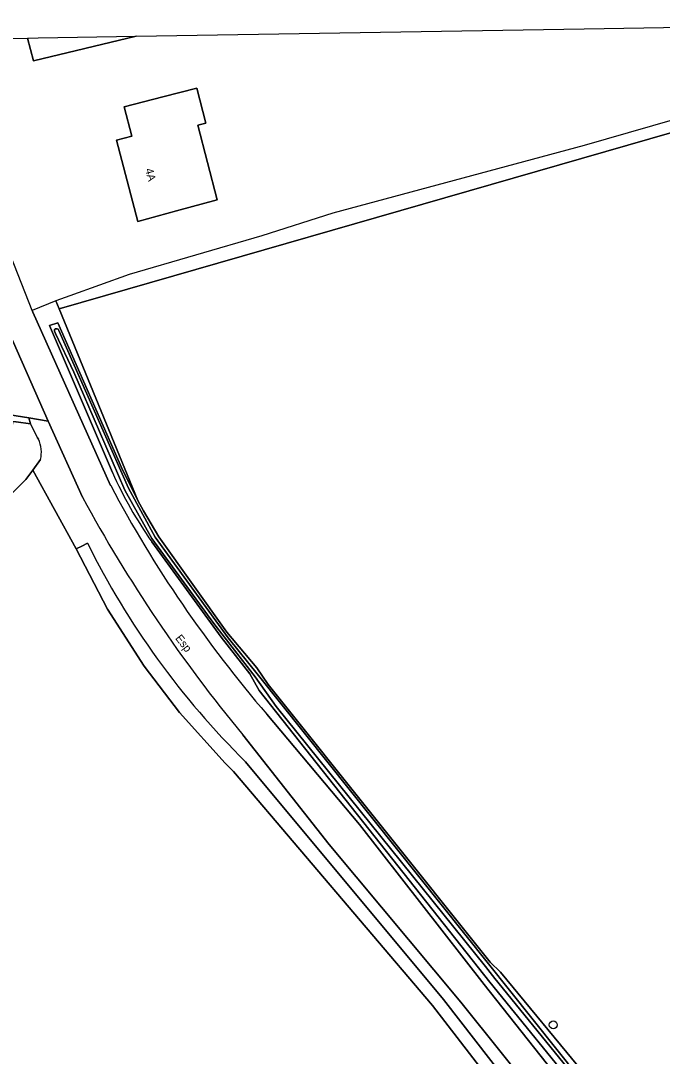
# Model space of a CAD drawing. Extents: x 161385 to 162589, y 388479 to 389756.
# Drawn here: x 162429.6 to 162509.8, y 389626.2 to 389755.6 of the extents above; entities that cross this region are included whole.
import ezdxf

# ---------------------------------------------------------------- set-up
doc = ezdxf.new("R2010")
doc.units = 0
for name, color, linetype in [('IMGEO_Boom', 7, 'Continuous'), ('IMGEO_Bouwland', 7, 'Continuous'), ('IMGEO_Erf', 7, 'Continuous'), ('IMGEO_Grasland_overig', 7, 'Continuous'), ('IMGEO_Groenvoorziening', 7, 'Continuous'), ('IMGEO_Hek', 7, 'Continuous'), ('IMGEO_Oever', 7, 'Continuous'), ('IMGEO_Openbare_ruimte_label', 7, 'Continuous'), ('IMGEO_Pand', 7, 'Continuous'), ('IMGEO_Pand_nummerreeks', 7, 'Continuous'), ('IMGEO_Rijbaan_lokaal_gesloten', 7, 'Continuous'), ('IMGEO_Rijbaan_lokaal_open', 7, 'Continuous'), ('IMGEO_Waterloop', 7, 'Continuous')]:
    doc.layers.add(name, color=color, linetype=linetype)

msp = doc.modelspace()

# ---------------------------------------------------------------- linework, layer by layer
at = {"layer": 'IMGEO_Boom'}
msp.add_circle((162496.15, 389630.11), 0.489, dxfattribs=at)
at = {"layer": 'IMGEO_Bouwland'}
for points in [[(162559.43, 389755.58), (162434.43, 389719.57), (162444.28, 389695.63), (162444.98, 389694.35), (162446.88, 389691.1), (162455.38, 389679.17), (162459.14, 389674.72), (162460.55, 389672.64), (162488.26, 389637.95), (162489.58, 389636.69), (162500, 389624.02)], [(162496.19, 389612.91), (162481.08, 389632.53), (162456.22, 389661.77), (162455.16, 389662.82), (162449.46, 389669.13), (162445.05, 389674.92), (162440.48, 389682.07), (162436.57, 389689.6), (162431.13, 389699.42), (162430.29, 389698.26), (162425.82, 389693.87), (162416.7, 389686.29), (162405.96, 389676.81), (162402.25, 389673.34), (162397.7, 389669.06), (162385.15, 389658.37), (162325.08, 389605.29), (162324.14, 389604.46), (162322.11, 389602.67), (162322.8, 389597.7), (162339.42, 389588), (162346.95, 389583.61), (162347.95, 389566.2), (162352.65, 389567.29)]]:
    msp.add_lwpolyline(points, dxfattribs=at)
at = {"layer": 'IMGEO_Erf'}
for points in [[(162444.07, 389753.64), (162500, 389754.58), (162552.12, 389755.46), (162552.12, 389755.46), (162552.12, 389755.46), (162534.43, 389750), (162528.09, 389748.05), (162500, 389739.97), (162468.6, 389731.52), (162459.77, 389728.7), (162443.19, 389723.89), (162435.78, 389721.2), (162434.02, 389720.56), (162431.05, 389719.38), (162426.09, 389732), (162425, 389736.75), (162419.72, 389750), (162418.44, 389753.21), (162430.5, 389753.41), (162431.25, 389750.55)], [(162451.63, 389747.16), (162452.77, 389742.79), (162451.76, 389742.53), (162454.18, 389733.21), (162449.11, 389731.82), (162444.28, 389730.5), (162441.6, 389740.67), (162443.51, 389741.17), (162442.55, 389744.8), (162447.39, 389746.06)]]:
    msp.add_lwpolyline(points, close=True, dxfattribs=at)
for points in [[(162444.07, 389753.64), (162431.25, 389750.55), (162430.5, 389753.41), (162431.8, 389753.43), (162444.07, 389753.64)], [(162428.38, 389704.2), (162428.56, 389705.01), (162428.62, 389705.29), (162428.66, 389705.5), (162429.02, 389705.46), (162429.08, 389705.45), (162430.85, 389705.23), (162430.63, 389705.94), (162416.62, 389708.17), (162415.83, 389707.79), (162364.15, 389682.86), (162364.04, 389682.81), (162386.14, 389662.75), (162389.24, 389665.14), (162390.05, 389665.76), (162402.57, 389677.34), (162410.94, 389684.45)]]:
    msp.add_lwpolyline(points, dxfattribs=at)
at = {"layer": 'IMGEO_Grasland_overig'}
msp.add_lwpolyline([(162559.43, 389755.58), (162552.12, 389755.46), (162552.12, 389755.46), (162534.43, 389750), (162528.09, 389748.05), (162500, 389739.97), (162468.6, 389731.52), (162459.77, 389728.7), (162443.19, 389723.89), (162435.78, 389721.2), (162434.02, 389720.56), (162434.43, 389719.57)], close=True, dxfattribs=at)
at = {"layer": 'IMGEO_Groenvoorziening'}
for points in [[(162441.08, 389699.13), (162433.24, 389717.49), (162434.28, 389717.85), (162442.23, 389699.76), (162444.28, 389695.63), (162434.43, 389719.57), (162434.02, 389720.56), (162431.05, 389719.38), (162431.13, 389719.17), (162440.87, 389697.49)], [(162437.34, 389696.04), (162433.05, 389705.55), (162430.63, 389705.94), (162430.85, 389705.23), (162431.75, 389703.46), (162431.84, 389703.29)], [(162432.1, 389700.75), (162431.13, 389699.42), (162436.57, 389689.6), (162437.27, 389689.94), (162437.99, 389690.29)], [(162500, 389620.97), (162488.25, 389635.43), (162459.4, 389671.88), (162458.24, 389673.98), (162454.69, 389678.56), (162446, 389690.46)], [(162460.38, 389668.93), (162471.96, 389655.14), (162487.54, 389635.16), (162500, 389619.35), (162502.33, 389616.39), (162507.6, 389609.95), (162508.18, 389609.16)], [(162484.59, 389632.95), (162468.15, 389652.66), (162457.37, 389666.34)], [(162457.73, 389662.99), (162482.44, 389633.29), (162495.86, 389616), (162501.86, 389608.05), (162500.82, 389607.06), (162500.28, 389606.55), (162496.89, 389610.48), (162485.48, 389604.32), (162481.25, 389602.12)], [(162499.72, 389614.08), (162484.59, 389632.95)]]:
    msp.add_lwpolyline(points, dxfattribs=at)
for centre, radius, start, end in [((162428.42, 389701.65), 3.8, 346.2941, 25.5475), ((162491.3, 389721.86), 55.12, 204.352, 214.7256), ((162577.72, 389770.02), 154.88, 207.9239, 220.748), ((162603.51, 389786.48), 189.19, 208.5573, 219.4218), ((162529.18, 389735.46), 101.77, 206.3483, 225.4052)]:
    msp.add_arc(centre, radius, start, end, dxfattribs=at)
at = {"layer": 'IMGEO_Hek'}
msp.add_lwpolyline([(162552.12, 389755.46), (162552.12, 389755.46), (162534.43, 389750), (162528.09, 389748.05), (162500, 389739.97), (162468.6, 389731.52), (162459.77, 389728.7), (162443.19, 389723.89), (162435.78, 389721.2), (162434.02, 389720.56)], dxfattribs=at)
at = {"layer": 'IMGEO_Oever'}
for points in [[(162500, 389624.02), (162489.58, 389636.69), (162488.26, 389637.95), (162460.55, 389672.64), (162459.14, 389674.72), (162455.38, 389679.17), (162446.88, 389691.1), (162444.98, 389694.35), (162444.28, 389695.63), (162442.23, 389699.76), (162434.28, 389717.85), (162433.24, 389717.49), (162441.08, 389699.13)], [(162500.61, 389621.47), (162488.87, 389635.92), (162487.69, 389637.41), (162461.54, 389669.89), (162458.93, 389673.58), (162453.77, 389680.28), (162446, 389690.88), (162442.64, 389696.93), (162439.47, 389704.26), (162436.26, 389711.68), (162433.99, 389716.5), (162433.87, 389716.79), (162433.87, 389716.98), (162433.96, 389717.1), (162434.08, 389717.1), (162434.19, 389717.1), (162434.31, 389717.05), (162434.41, 389716.89), (162437.9, 389708.98), (162443.11, 389697.18), (162446.43, 389691.07), (162455.53, 389678.48), (162459.32, 389673.75), (162499.39, 389623.53)], [(162446, 389690.46), (162454.69, 389678.56), (162458.24, 389673.98), (162459.4, 389671.88), (162488.25, 389635.43), (162500, 389620.97)]]:
    msp.add_lwpolyline(points, dxfattribs=at)
msp.add_arc((162491.3, 389721.86), 55.12, 204.352, 214.7256, dxfattribs=at)
at = {"layer": 'IMGEO_Pand'}
msp.add_lwpolyline([(162447.39, 389746.06), (162442.55, 389744.8), (162443.51, 389741.17), (162441.6, 389740.67), (162444.28, 389730.5), (162449.11, 389731.82), (162454.18, 389733.21), (162451.76, 389742.53), (162452.77, 389742.79), (162451.63, 389747.16)], close=True, dxfattribs=at)
at = {"layer": 'IMGEO_Rijbaan_lokaal_gesloten'}
for points in [[(162440.87, 389697.49), (162431.13, 389719.17), (162431.05, 389719.38), (162426.09, 389732), (162425, 389736.75), (162419.72, 389750), (162418.44, 389753.21), (162414.27, 389753.14), (162414.24, 389753.14)], [(162414.24, 389753.14), (162414.82, 389751.67), (162426.99, 389719.26), (162433.05, 389705.55), (162437.34, 389696.04)], [(162508.18, 389609.16), (162507.6, 389609.95), (162502.33, 389616.39), (162500, 389619.35), (162487.54, 389635.16), (162471.96, 389655.14), (162460.38, 389668.93)], [(162457.37, 389666.34), (162468.15, 389652.66), (162484.59, 389632.95), (162499.72, 389614.08), (162500, 389613.71), (162504.04, 389608.44), (162504.07, 389608.41), (162504.38, 389607.97), (162504.65, 389607.5), (162504.88, 389607.01), (162505.07, 389606.5), (162505.21, 389605.98), (162505.3, 389605.44), (162505.32, 389605.29), (162505.35, 389604.9), (162505.34, 389604.36), (162505.29, 389603.82), (162505.19, 389603.29), (162505.04, 389602.77), (162504.85, 389602.26), (162504.61, 389601.78), (162504.33, 389601.31), (162504.01, 389600.88)]]:
    msp.add_lwpolyline(points, dxfattribs=at)
for centre, radius, start, end in [((162577.72, 389770.02), 154.88, 207.9239, 220.748), ((162603.51, 389786.48), 189.19, 208.5573, 219.4218)]:
    msp.add_arc(centre, radius, start, end, dxfattribs=at)
at = {"layer": 'IMGEO_Rijbaan_lokaal_open'}
msp.add_lwpolyline([(162426.99, 389719.26), (162424.48, 389717.71), (162415.11, 389711.94), (162414.14, 389711.47), (162415.83, 389707.79), (162416.62, 389708.17), (162430.63, 389705.94), (162433.05, 389705.55)], close=True, dxfattribs=at)
at = {"layer": 'IMGEO_Waterloop'}
for points in [[(162499.39, 389623.53), (162459.32, 389673.75), (162455.53, 389678.48), (162446.43, 389691.07), (162443.11, 389697.18), (162437.9, 389708.98), (162434.41, 389716.89), (162434.31, 389717.05), (162434.19, 389717.1), (162434.08, 389717.1), (162433.96, 389717.1), (162433.87, 389716.98), (162433.87, 389716.79), (162433.99, 389716.5), (162436.26, 389711.68), (162439.47, 389704.26), (162442.64, 389696.93), (162446, 389690.88), (162453.77, 389680.28), (162458.93, 389673.58), (162461.54, 389669.89), (162487.69, 389637.41), (162488.87, 389635.92), (162500.61, 389621.47)], [(162431.84, 389703.29), (162431.75, 389703.46), (162430.85, 389705.23), (162429.08, 389705.45), (162429.02, 389705.46), (162428.66, 389705.5), (162428.62, 389705.29), (162428.56, 389705.01), (162428.38, 389704.2)], [(162416.7, 389686.29), (162425.82, 389693.87), (162430.29, 389698.26), (162431.13, 389699.42), (162432.1, 389700.75)], [(162437.99, 389690.29), (162437.27, 389689.94), (162436.57, 389689.6), (162440.48, 389682.07), (162445.05, 389674.92), (162449.46, 389669.13), (162455.16, 389662.82), (162456.22, 389661.77), (162481.08, 389632.53), (162496.19, 389612.91), (162480.12, 389604.24)], [(162481.25, 389602.12), (162485.48, 389604.32), (162496.89, 389610.48), (162500.28, 389606.55), (162500.82, 389607.06), (162501.86, 389608.05), (162495.86, 389616), (162482.44, 389633.29), (162457.73, 389662.99)]]:
    msp.add_lwpolyline(points, dxfattribs=at)
for centre, radius, start, end in [((162428.42, 389701.65), 3.8, 346.2941, 25.5475), ((162529.18, 389735.46), 101.77, 206.3483, 225.4052)]:
    msp.add_arc(centre, radius, start, end, dxfattribs=at)

# ---------------------------------------------------------------- texts
at = {"layer": 'IMGEO_Openbare_ruimte_label'}
msp.add_text('Esp', height=1, rotation=307.8097, dxfattribs=at).set_placement((162448.89, 389678.4))
at = {"layer": 'IMGEO_Pand_nummerreeks'}
msp.add_text('4A', height=1, rotation=284.7857, dxfattribs=at).set_placement((162445.17, 389737.01))

doc.saveas('drawing.dxf')
